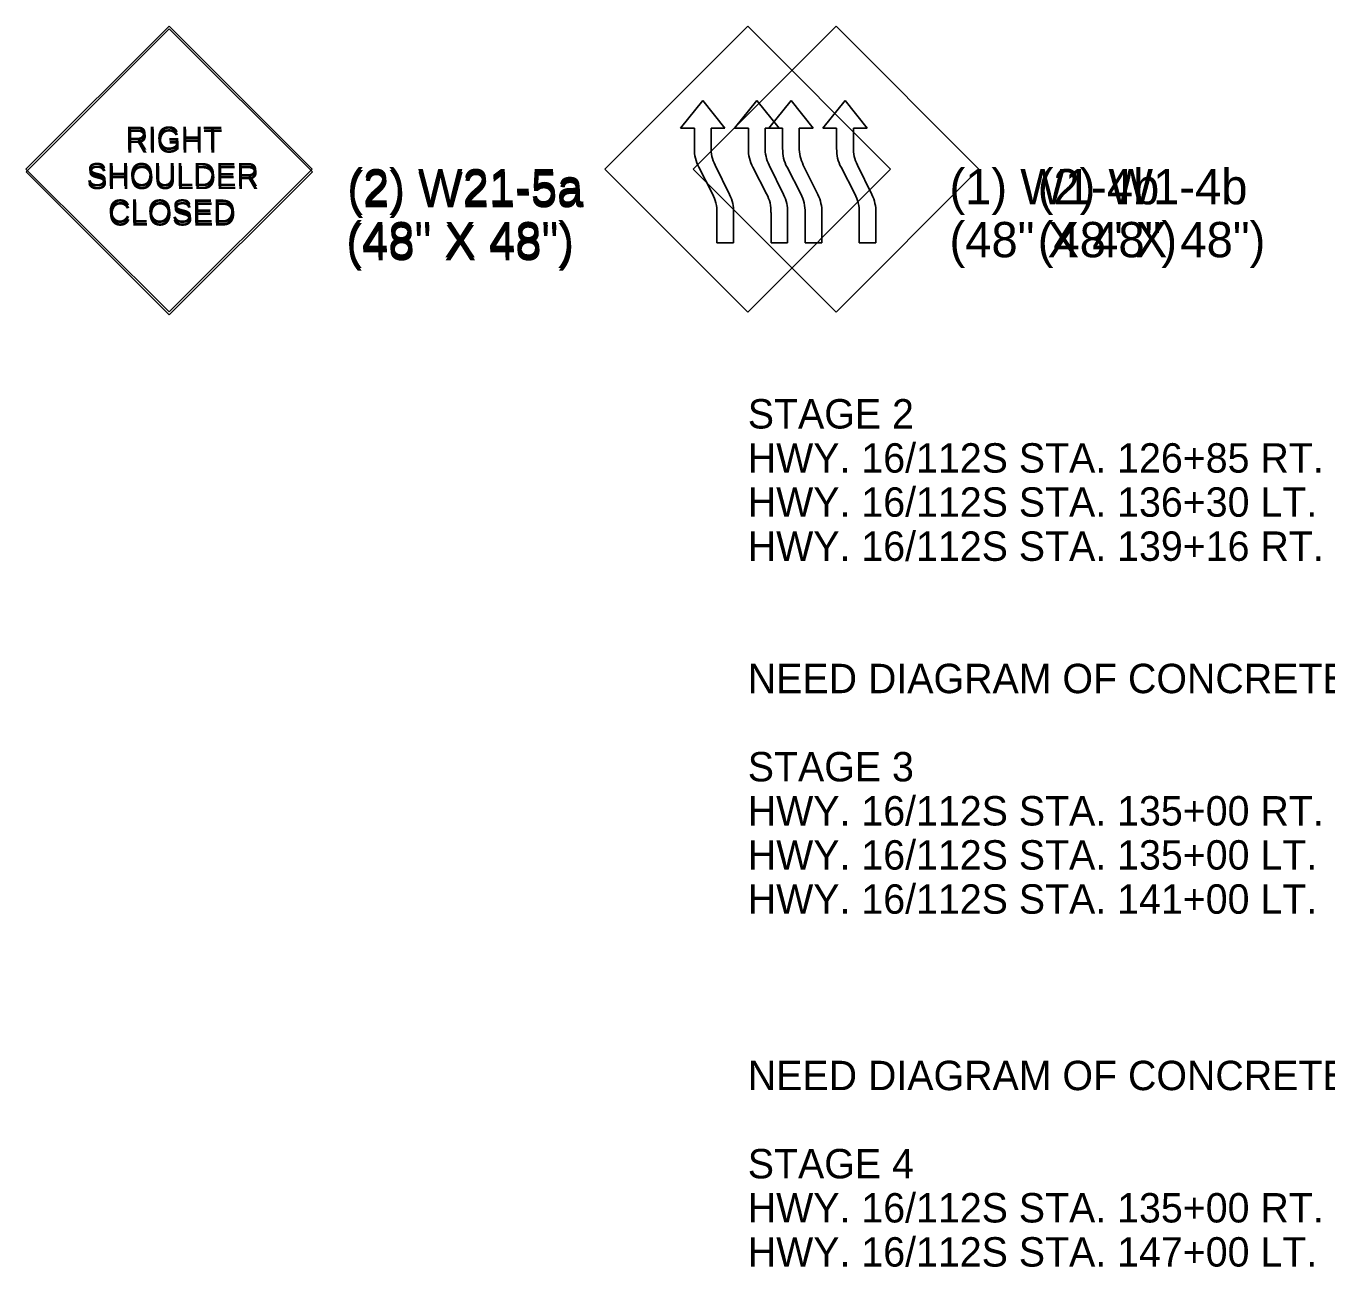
# Model space of a CAD drawing. Extents: x 659657 to 668193, y 633084 to 648639.
# Drawn here: x 662181.2 to 662402.2, y 640063.2 to 640274.2 of the extents above; entities that cross this region are included whole.
import ezdxf

# ---------------------------------------------------------------- set-up
doc = ezdxf.new("R2010")
doc.units = 0
for name, color, linetype in [('R_Draft', 7, 'Continuous'), ('R_ROW Annot', 7, 'Continuous'), ('T_Notes', 7, 'Continuous'), ('T_SIGNAL CONTROL CABINET', 7, 'Continuous'), ('TEMP_DETECTION ZONE_Stage 2', 7, 'Continuous'), ('TEMP_SIGNAL_HEAD_STAGE 2', 7, 'Continuous'), ('TEXT_TEMP_SIGNAL_POLES_STAGE 2', 7, 'Continuous')]:
    doc.layers.add(name, color=color, linetype=linetype)

msp = doc.modelspace()

# ---------------------------------------------------------------- linework, layer by layer
at = {"layer": 'R_Draft'}
for p, q in [((662279.59, 640249.84), (662303.9, 640274.15)), ((662328.19, 640249.84), (662303.9, 640274.15)), ((662292.47, 640256.79), (662296.25, 640261.5)), ((662296.25, 640261.5), (662300.02, 640256.79)), ((662301.65, 640256.79), (662305.43, 640261.5)), ((662305.43, 640261.5), (662309.21, 640256.79)), ((662294.83, 640256.79), (662292.47, 640256.79)), ((662294.83, 640253.33), (662294.83, 640256.79)), ((662300.02, 640256.79), (662297.66, 640256.79)), ((662297.66, 640256.79), (662297.66, 640253.56)), ((662304.01, 640256.79), (662301.65, 640256.79)), ((662304.01, 640253.33), (662304.01, 640256.79)), ((662309.21, 640256.79), (662306.85, 640256.79)), ((662306.85, 640256.79), (662306.85, 640253.56)), ((662298.34, 640250.5), (662300.82, 640245.5)), ((662307.53, 640250.5), (662310, 640245.5)), ((662303.9, 640225.53), (662279.59, 640249.84)), ((662297.92, 640245.62), (662295.57, 640250.15)), ((662303.9, 640225.53), (662328.19, 640249.84)), ((662307.11, 640245.62), (662304.75, 640250.15)), ((662298.66, 640237.32), (662298.66, 640242.44)), ((662301.5, 640242.44), (662301.5, 640237.32)), ((662307.85, 640237.32), (662307.85, 640242.44)), ((662310.68, 640242.44), (662310.68, 640237.32)), ((662301.5, 640237.32), (662298.66, 640237.32)), ((662310.68, 640237.32), (662307.85, 640237.32))]:
    msp.add_line(p, q, dxfattribs=at)
for centre, major_axis, end_param in [((662301.88, 640253.17), (-7.05, 0), 6.745846), ((662304.71, 640253.41), (-7.05, 0), 6.726719), ((662311.06, 640253.17), (-7.05, 0), 6.745846), ((662313.9, 640253.41), (-7.05, 0), 6.726719), ((662291.61, 640242.59), (7.05, 0), 6.745846), ((662294.45, 640242.59), (7.05, 0), 6.726719), ((662300.8, 640242.59), (7.05, 0), 6.745846), ((662303.63, 640242.59), (7.05, 0), 6.726719)]:
    msp.add_ellipse(centre, major_axis=major_axis, ratio=0.96, start_param=6.26006, end_param=end_param, dxfattribs=at)
at = {"layer": 'R_ROW Annot'}
for p, q in [((662279.59, 640249.84), (662303.9, 640274.15)), ((662328.19, 640249.84), (662303.9, 640274.15)), ((662292.47, 640256.79), (662296.25, 640261.5)), ((662296.25, 640261.5), (662300.02, 640256.79)), ((662301.65, 640256.79), (662305.43, 640261.5)), ((662305.43, 640261.5), (662309.21, 640256.79)), ((662294.83, 640256.79), (662292.47, 640256.79)), ((662294.83, 640253.33), (662294.83, 640256.79)), ((662300.02, 640256.79), (662297.66, 640256.79)), ((662297.66, 640256.79), (662297.66, 640253.56)), ((662304.01, 640256.79), (662301.65, 640256.79)), ((662304.01, 640253.33), (662304.01, 640256.79)), ((662309.21, 640256.79), (662306.85, 640256.79)), ((662306.85, 640256.79), (662306.85, 640253.56)), ((662298.34, 640250.5), (662300.82, 640245.5)), ((662307.53, 640250.5), (662310, 640245.5)), ((662303.9, 640225.53), (662279.59, 640249.84)), ((662297.92, 640245.62), (662295.57, 640250.15)), ((662303.9, 640225.53), (662328.19, 640249.84)), ((662307.11, 640245.62), (662304.75, 640250.15)), ((662298.66, 640237.32), (662298.66, 640242.44)), ((662301.5, 640242.44), (662301.5, 640237.32)), ((662307.85, 640237.32), (662307.85, 640242.44)), ((662310.68, 640242.44), (662310.68, 640237.32)), ((662301.5, 640237.32), (662298.66, 640237.32)), ((662310.68, 640237.32), (662307.85, 640237.32))]:
    msp.add_line(p, q, dxfattribs=at)
for centre, major_axis, end_param in [((662301.88, 640253.17), (-7.05, 0), 6.745846), ((662304.71, 640253.41), (-7.05, 0), 6.726719), ((662311.06, 640253.17), (-7.05, 0), 6.745846), ((662313.9, 640253.41), (-7.05, 0), 6.726719), ((662291.61, 640242.59), (7.05, 0), 6.745846), ((662294.45, 640242.59), (7.05, 0), 6.726719), ((662300.8, 640242.59), (7.05, 0), 6.745846), ((662303.63, 640242.59), (7.05, 0), 6.726719)]:
    msp.add_ellipse(centre, major_axis=major_axis, ratio=0.96, start_param=6.26006, end_param=end_param, dxfattribs=at)
at = {"layer": 'T_Notes'}
for p, q in [((662279.59, 640249.84), (662303.9, 640274.15)), ((662328.19, 640249.84), (662303.9, 640274.15)), ((662292.47, 640256.79), (662296.25, 640261.5)), ((662296.25, 640261.5), (662300.02, 640256.79)), ((662301.65, 640256.79), (662305.43, 640261.5)), ((662305.43, 640261.5), (662309.21, 640256.79)), ((662294.83, 640256.79), (662292.47, 640256.79)), ((662294.83, 640253.33), (662294.83, 640256.79)), ((662300.02, 640256.79), (662297.66, 640256.79)), ((662297.66, 640256.79), (662297.66, 640253.56)), ((662304.01, 640256.79), (662301.65, 640256.79)), ((662304.01, 640253.33), (662304.01, 640256.79)), ((662309.21, 640256.79), (662306.85, 640256.79)), ((662306.85, 640256.79), (662306.85, 640253.56)), ((662298.34, 640250.5), (662300.82, 640245.5)), ((662307.53, 640250.5), (662310, 640245.5)), ((662303.9, 640225.53), (662279.59, 640249.84)), ((662297.92, 640245.62), (662295.57, 640250.15)), ((662303.9, 640225.53), (662328.19, 640249.84)), ((662307.11, 640245.62), (662304.75, 640250.15)), ((662298.66, 640237.32), (662298.66, 640242.44)), ((662301.5, 640242.44), (662301.5, 640237.32)), ((662307.85, 640237.32), (662307.85, 640242.44)), ((662310.68, 640242.44), (662310.68, 640237.32)), ((662301.5, 640237.32), (662298.66, 640237.32)), ((662310.68, 640237.32), (662307.85, 640237.32))]:
    msp.add_line(p, q, dxfattribs=at)
for centre, major_axis, end_param in [((662301.88, 640253.17), (-7.05, 0), 6.745846), ((662304.71, 640253.41), (-7.05, 0), 6.726719), ((662311.06, 640253.17), (-7.05, 0), 6.745846), ((662313.9, 640253.41), (-7.05, 0), 6.726719), ((662291.61, 640242.59), (7.05, 0), 6.745846), ((662294.45, 640242.59), (7.05, 0), 6.726719), ((662300.8, 640242.59), (7.05, 0), 6.745846), ((662303.63, 640242.59), (7.05, 0), 6.726719)]:
    msp.add_ellipse(centre, major_axis=major_axis, ratio=0.96, start_param=6.26006, end_param=end_param, dxfattribs=at)
at = {"layer": 'TEMP_DETECTION ZONE_Stage 2'}
for p, q in [((662205.51, 640274.16), (662181.19, 640249.84)), ((662229.83, 640249.84), (662205.51, 640274.16)), ((662294.59, 640249.84), (662318.9, 640274.15)), ((662343.19, 640249.84), (662318.9, 640274.15)), ((662307.47, 640256.79), (662311.25, 640261.5)), ((662311.25, 640261.5), (662315.02, 640256.79)), ((662316.65, 640256.79), (662320.43, 640261.5)), ((662320.43, 640261.5), (662324.21, 640256.79)), ((662309.83, 640256.79), (662307.47, 640256.79)), ((662309.83, 640253.33), (662309.83, 640256.79)), ((662315.02, 640256.79), (662312.66, 640256.79)), ((662312.66, 640256.79), (662312.66, 640253.56)), ((662319.01, 640256.79), (662316.65, 640256.79)), ((662319.01, 640253.33), (662319.01, 640256.79)), ((662324.21, 640256.79), (662321.85, 640256.79)), ((662321.85, 640256.79), (662321.85, 640253.56)), ((662313.34, 640250.5), (662315.82, 640245.5)), ((662322.53, 640250.5), (662325, 640245.5)), ((662205.51, 640225.54), (662181.19, 640249.84)), ((662229.83, 640249.84), (662205.51, 640225.54)), ((662318.9, 640225.53), (662294.59, 640249.84)), ((662312.92, 640245.62), (662310.57, 640250.15)), ((662318.9, 640225.53), (662343.19, 640249.84)), ((662322.11, 640245.62), (662319.75, 640250.15)), ((662313.66, 640237.32), (662313.66, 640242.44)), ((662316.5, 640242.44), (662316.5, 640237.32)), ((662322.85, 640237.32), (662322.85, 640242.44)), ((662325.68, 640242.44), (662325.68, 640237.32)), ((662316.5, 640237.32), (662313.66, 640237.32)), ((662325.68, 640237.32), (662322.85, 640237.32))]:
    msp.add_line(p, q, dxfattribs=at)
for centre, major_axis, end_param in [((662316.88, 640253.17), (-7.05, 0), 6.745846), ((662319.71, 640253.41), (-7.05, 0), 6.726719), ((662326.06, 640253.17), (-7.05, 0), 6.745846), ((662328.9, 640253.41), (-7.05, 0), 6.726719), ((662306.61, 640242.59), (7.05, 0), 6.745846), ((662309.45, 640242.59), (7.05, 0), 6.726719), ((662315.8, 640242.59), (7.05, 0), 6.745846), ((662318.63, 640242.59), (7.05, 0), 6.726719)]:
    msp.add_ellipse(centre, major_axis=major_axis, ratio=0.96, start_param=6.26006, end_param=end_param, dxfattribs=at)
at = {"layer": 'TEMP_SIGNAL_HEAD_STAGE 2'}
for p, q in [((662205.56, 640273.66), (662181.24, 640249.34)), ((662229.88, 640249.34), (662205.56, 640273.66)), ((662294.59, 640249.84), (662318.9, 640274.15)), ((662343.19, 640249.84), (662318.9, 640274.15)), ((662307.47, 640256.79), (662311.25, 640261.5)), ((662311.25, 640261.5), (662315.02, 640256.79)), ((662316.65, 640256.79), (662320.43, 640261.5)), ((662320.43, 640261.5), (662324.21, 640256.79)), ((662309.83, 640256.79), (662307.47, 640256.79)), ((662309.83, 640253.33), (662309.83, 640256.79)), ((662315.02, 640256.79), (662312.66, 640256.79)), ((662312.66, 640256.79), (662312.66, 640253.56)), ((662319.01, 640256.79), (662316.65, 640256.79)), ((662319.01, 640253.33), (662319.01, 640256.79)), ((662324.21, 640256.79), (662321.85, 640256.79)), ((662321.85, 640256.79), (662321.85, 640253.56)), ((662313.34, 640250.5), (662315.82, 640245.5)), ((662322.53, 640250.5), (662325, 640245.5)), ((662205.56, 640225.04), (662181.24, 640249.34)), ((662229.88, 640249.34), (662205.56, 640225.04)), ((662318.9, 640225.53), (662294.59, 640249.84)), ((662312.92, 640245.62), (662310.57, 640250.15)), ((662318.9, 640225.53), (662343.19, 640249.84)), ((662322.11, 640245.62), (662319.75, 640250.15)), ((662313.66, 640237.32), (662313.66, 640242.44)), ((662316.5, 640242.44), (662316.5, 640237.32)), ((662322.85, 640237.32), (662322.85, 640242.44)), ((662325.68, 640242.44), (662325.68, 640237.32)), ((662316.5, 640237.32), (662313.66, 640237.32)), ((662325.68, 640237.32), (662322.85, 640237.32))]:
    msp.add_line(p, q, dxfattribs=at)
for centre, major_axis, end_param in [((662316.88, 640253.17), (-7.05, 0), 6.745846), ((662319.71, 640253.41), (-7.05, 0), 6.726719), ((662326.06, 640253.17), (-7.05, 0), 6.745846), ((662328.9, 640253.41), (-7.05, 0), 6.726719), ((662306.61, 640242.59), (7.05, 0), 6.745846), ((662309.45, 640242.59), (7.05, 0), 6.726719), ((662315.8, 640242.59), (7.05, 0), 6.745846), ((662318.63, 640242.59), (7.05, 0), 6.726719)]:
    msp.add_ellipse(centre, major_axis=major_axis, ratio=0.96, start_param=6.26006, end_param=end_param, dxfattribs=at)
at = {"layer": 'TEXT_TEMP_SIGNAL_POLES_STAGE 2'}
for p, q in [((662205.56, 640273.66), (662181.24, 640249.34)), ((662229.88, 640249.34), (662205.56, 640273.66)), ((662294.59, 640249.84), (662318.9, 640274.15)), ((662343.19, 640249.84), (662318.9, 640274.15)), ((662307.47, 640256.79), (662311.25, 640261.5)), ((662311.25, 640261.5), (662315.02, 640256.79)), ((662316.65, 640256.79), (662320.43, 640261.5)), ((662320.43, 640261.5), (662324.21, 640256.79)), ((662309.83, 640256.79), (662307.47, 640256.79)), ((662309.83, 640253.33), (662309.83, 640256.79)), ((662315.02, 640256.79), (662312.66, 640256.79)), ((662312.66, 640256.79), (662312.66, 640253.56)), ((662319.01, 640256.79), (662316.65, 640256.79)), ((662319.01, 640253.33), (662319.01, 640256.79)), ((662324.21, 640256.79), (662321.85, 640256.79)), ((662321.85, 640256.79), (662321.85, 640253.56)), ((662313.34, 640250.5), (662315.82, 640245.5)), ((662322.53, 640250.5), (662325, 640245.5)), ((662205.56, 640225.04), (662181.24, 640249.34)), ((662229.88, 640249.34), (662205.56, 640225.04)), ((662318.9, 640225.53), (662294.59, 640249.84)), ((662312.92, 640245.62), (662310.57, 640250.15)), ((662318.9, 640225.53), (662343.19, 640249.84)), ((662322.11, 640245.62), (662319.75, 640250.15)), ((662313.66, 640237.32), (662313.66, 640242.44)), ((662316.5, 640242.44), (662316.5, 640237.32)), ((662322.85, 640237.32), (662322.85, 640242.44)), ((662325.68, 640242.44), (662325.68, 640237.32)), ((662316.5, 640237.32), (662313.66, 640237.32)), ((662325.68, 640237.32), (662322.85, 640237.32))]:
    msp.add_line(p, q, dxfattribs=at)
for centre, major_axis, end_param in [((662316.88, 640253.17), (-7.05, 0), 6.745846), ((662319.71, 640253.41), (-7.05, 0), 6.726719), ((662326.06, 640253.17), (-7.05, 0), 6.745846), ((662328.9, 640253.41), (-7.05, 0), 6.726719), ((662306.61, 640242.59), (7.05, 0), 6.745846), ((662309.45, 640242.59), (7.05, 0), 6.726719), ((662315.8, 640242.59), (7.05, 0), 6.745846), ((662318.63, 640242.59), (7.05, 0), 6.726719)]:
    msp.add_ellipse(centre, major_axis=major_axis, ratio=0.96, start_param=6.26006, end_param=end_param, dxfattribs=at)

# ---------------------------------------------------------------- texts
at = {"layer": 'R_Draft'}
for s, p in [('(1) W1-4b', (662338.19, 640243.84)), ('(48" X 48")', (662338.19, 640234.84))]:
    msp.add_text(s, height=6, dxfattribs=at).set_placement(p)
at = {"layer": 'R_ROW Annot'}
for s, p in [('(1) W1-4b', (662338.19, 640243.84)), ('(48" X 48")', (662338.19, 640234.84))]:
    msp.add_text(s, height=6, dxfattribs=at).set_placement(p)
at = {"layer": 'T_Notes'}
for s, p in [('(1) W1-4b', (662338.19, 640243.84)), ('(48" X 48")', (662338.19, 640234.84))]:
    msp.add_text(s, height=6, dxfattribs=at).set_placement(p)
at = {"layer": 'T_SIGNAL CONTROL CABINET'}
for s, p in [('STAGE 2', (662303.9, 640205.72)), ('HWY. 16/112S STA. 126+85 RT.', (662303.9, 640198.22)), ('HWY. 16/112S STA. 136+30 LT.', (662303.9, 640190.72)), ('HWY. 16/112S STA. 139+16 RT.', (662303.9, 640183.22)), ('NEED DIAGRAM OF CONCRETE BARRIER WITH ATTENUATOR (BARRIER PLACED ALONG EDGE OF LANE)', (662303.9, 640160.72)), ('STAGE 3', (662303.9, 640145.72)), ('HWY. 16/112S STA. 135+00 RT.', (662303.9, 640138.22)), ('HWY. 16/112S STA. 135+00 LT.', (662303.9, 640130.72)), ('HWY. 16/112S STA. 141+00 LT.', (662303.9, 640123.22)), ("NEED DIAGRAM OF CONCRETE BARRIER WITH ATTENUATOR (BARRIER PLACED 2' FROM EDGE OF LANE)", (662303.9, 640093.22)), ('STAGE 4', (662303.9, 640078.22)), ('HWY. 16/112S STA. 135+00 RT.', (662303.9, 640070.72)), ('HWY. 16/112S STA. 147+00 LT.', (662303.9, 640063.22))]:
    msp.add_text(s, height=5, dxfattribs=at).set_placement(p)
at = {"layer": 'TEMP_DETECTION ZONE_Stage 2'}
for s, rotation, p in [('RIGHT', 359.999, (662198.12, 640253.13)), ('SHOULDER', 359.9986, (662191.48, 640246.93)), ('CLOSED', 359.9986, (662195.14, 640240.73))]:
    msp.add_text(s, height=3.94, rotation=rotation, dxfattribs=at).set_placement(p)
for s, p in [('(2) W21-5a', (662235.8, 640243.84)), ('(2) W1-4b', (662353.19, 640243.84)), ('(48" X 48")', (662235.63, 640234.84)), ('(48" X 48")', (662353.19, 640234.84))]:
    msp.add_text(s, height=6, dxfattribs=at).set_placement(p)
at = {"layer": 'TEMP_SIGNAL_HEAD_STAGE 2'}
for s, rotation, p in [('RIGHT', 359.999, (662198.17, 640252.63)), ('SHOULDER', 359.9986, (662191.54, 640246.43)), ('CLOSED', 359.9986, (662195.2, 640240.23))]:
    msp.add_text(s, height=3.94, rotation=rotation, dxfattribs=at).set_placement(p)
for s, p in [('(2) W21-5a', (662235.85, 640243.34)), ('(2) W1-4b', (662353.19, 640243.84)), ('(48" X 48")', (662235.68, 640234.34)), ('(48" X 48")', (662353.19, 640234.84))]:
    msp.add_text(s, height=6, dxfattribs=at).set_placement(p)
at = {"layer": 'TEXT_TEMP_SIGNAL_POLES_STAGE 2'}
for s, rotation, p in [('RIGHT', 359.999, (662198.17, 640252.63)), ('SHOULDER', 359.9986, (662191.54, 640246.43)), ('CLOSED', 359.9986, (662195.2, 640240.23))]:
    msp.add_text(s, height=3.94, rotation=rotation, dxfattribs=at).set_placement(p)
for s, p in [('(2) W21-5a', (662235.85, 640243.34)), ('(2) W1-4b', (662353.19, 640243.84)), ('(48" X 48")', (662235.68, 640234.34)), ('(48" X 48")', (662353.19, 640234.84))]:
    msp.add_text(s, height=6, dxfattribs=at).set_placement(p)

doc.saveas('drawing.dxf')
